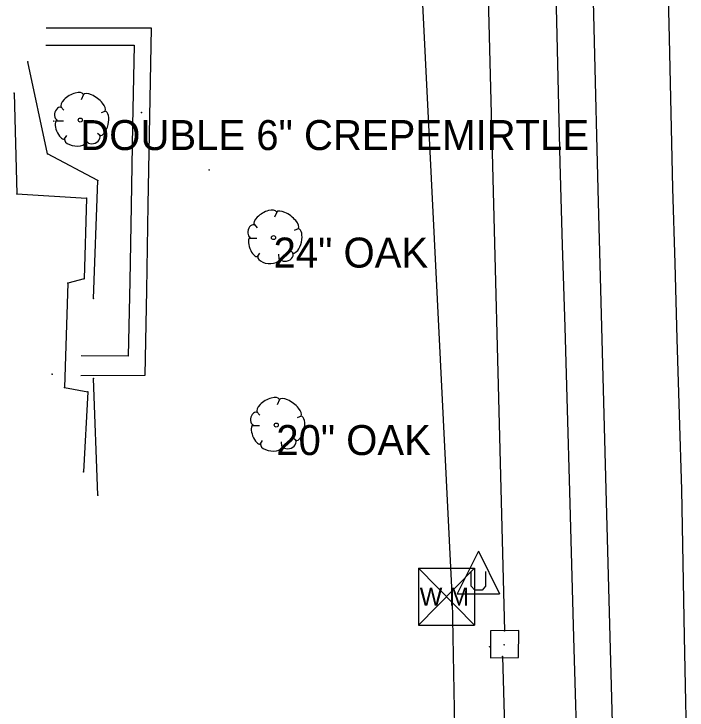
# Model space of a CAD drawing. Extents: x 1930288 to 1941089, y 588389 to 611475.
# Drawn here: x 1930777.7 to 1930890, y 597559.1 to 597675.1 of the extents above; entities that cross this region are included whole.
import ezdxf

# ---------------------------------------------------------------- set-up
doc = ezdxf.new("R2010")
doc.units = 0
for name, color, linetype in [('S_BUILDING', 7, 'Continuous'), ('S_DRG_PT_SYM', 7, 'Continuous'), ('S_DROP_INLET', 7, 'Continuous'), ('S_EDGE_PAVEMENT', 7, 'Continuous'), ('S_MSC_PT_SYM', 7, 'Continuous'), ('S_PAVEMENT_CROWN', 7, 'Continuous'), ('S_SHOULDER', 7, 'Continuous'), ('S_SIDEWALK', 7, 'Continuous'), ('S_STORM_SEWER', 7, 'Continuous'), ('S_STR_PT_SYM', 7, 'Continuous'), ('S_TREE', 7, 'Continuous'), ('S_TREE_ANNOT', 7, 'Continuous'), ('S_UNDERGROUND_CABLE', 7, 'Continuous'), ('S_UTL_PT_SYM', 7, 'Continuous'), ('S_WATER_UTILITIES', 7, 'Continuous')]:
    doc.layers.add(name, color=color, linetype=linetype)

msp = doc.modelspace()

# ---------------------------------------------------------------- linework, layer by layer
at = {"layer": 'S_BUILDING'}
for p, q in [((1930777.79, 597661.9), (1930778.25, 597645.11)), ((1930778.25, 597645.11), (1930789.85, 597644.43)), ((1930789.85, 597644.43), (1930789.43, 597630.99)), ((1930786.71, 597630.23), (1930786.18, 597612.84)), ((1930789.43, 597630.99), (1930786.71, 597630.23)), ((1930786.18, 597612.84), (1930790.09, 597612.14)), ((1930790.09, 597612.14), (1930789.32, 597598.78))]:
    msp.add_line(p, q, dxfattribs=at)
at = {"layer": 'S_DRG_PT_SYM'}
msp.add_lwpolyline([(1930859.51, 597569.98), (1930859.51, 597570.03), (1930859.51, 597569.98), (1930859.46, 597569.98), (1930859.51, 597569.98), (1930859.51, 597569.93), (1930859.51, 597569.98), (1930859.56, 597569.98)], dxfattribs=at)
at = {"layer": 'S_DROP_INLET'}
for points in [[(1930857.24, 597572.29), (1930857.22, 597567.78), (1930861.91, 597567.86), (1930861.93, 597572.36)], [(1930861.93, 597572.36), (1930857.24, 597572.29)]]:
    msp.add_lwpolyline(points, dxfattribs=at)
at = {"layer": 'S_EDGE_PAVEMENT'}
msp.add_lwpolyline([(1930870.73, 597810.89), (1930871.29, 597787.65), (1930871.95, 597765.34), (1930872.62, 597743.02), (1930873.25, 597719.11), (1930873.88, 597695.2), (1930874.49, 597670.52), (1930875.1, 597645.85), (1930875.43, 597633.35), (1930875.77, 597620.85), (1930876.1, 597608.34), (1930876.44, 597595.84), (1930877.12, 597571.29), (1930877.79, 597546.75)], dxfattribs=at)
at = {"layer": 'S_MSC_PT_SYM'}
for points in [[(1930780.05, 597667.14), (1930780.05, 597667.19), (1930780.05, 597667.14), (1930780, 597667.14), (1930780.05, 597667.14), (1930780.05, 597667.09), (1930780.05, 597667.14), (1930780.1, 597667.14)], [(1930799.01, 597658.7), (1930799.01, 597658.75), (1930799.01, 597658.7), (1930798.96, 597658.7), (1930799.01, 597658.7), (1930799.01, 597658.65), (1930799.01, 597658.7), (1930799.06, 597658.7)], [(1930784.38, 597657.27), (1930784.38, 597657.32), (1930784.38, 597657.27), (1930784.33, 597657.27), (1930784.38, 597657.27), (1930784.38, 597657.22), (1930784.38, 597657.27), (1930784.43, 597657.27)], [(1930783.36, 597651.78), (1930783.36, 597651.83), (1930783.36, 597651.78), (1930783.31, 597651.78), (1930783.36, 597651.78), (1930783.36, 597651.73), (1930783.36, 597651.78), (1930783.41, 597651.78)], [(1930810.3, 597649.11), (1930810.3, 597649.16), (1930810.3, 597649.11), (1930810.25, 597649.11), (1930810.3, 597649.11), (1930810.3, 597649.06), (1930810.3, 597649.11), (1930810.35, 597649.11)], [(1930791.76, 597647.37), (1930791.76, 597647.42), (1930791.76, 597647.37), (1930791.71, 597647.37), (1930791.76, 597647.37), (1930791.76, 597647.32), (1930791.76, 597647.37), (1930791.81, 597647.37)], [(1930790.99, 597627.66), (1930790.99, 597627.71), (1930790.99, 597627.66), (1930790.94, 597627.66), (1930790.99, 597627.66), (1930790.99, 597627.61), (1930790.99, 597627.66), (1930791.04, 597627.66)], [(1930784.1, 597615.07), (1930784.1, 597615.12), (1930784.1, 597615.07), (1930784.05, 597615.07), (1930784.1, 597615.07), (1930784.1, 597615.02), (1930784.1, 597615.07), (1930784.15, 597615.07)], [(1930790.99, 597614.35), (1930790.99, 597614.4), (1930790.99, 597614.35), (1930790.94, 597614.35), (1930790.99, 597614.35), (1930790.99, 597614.3), (1930790.99, 597614.35), (1930791.04, 597614.35)], [(1930791.72, 597594.91), (1930791.72, 597594.96), (1930791.72, 597594.91), (1930791.67, 597594.91), (1930791.72, 597594.91), (1930791.72, 597594.86), (1930791.72, 597594.91), (1930791.77, 597594.91)], [(1930859.53, 597572.29), (1930859.53, 597572.34), (1930859.53, 597572.29), (1930859.48, 597572.29), (1930859.53, 597572.29), (1930859.53, 597572.24), (1930859.53, 597572.29), (1930859.58, 597572.29)], [(1930857.03, 597569.65), (1930857.03, 597569.7), (1930857.03, 597569.65), (1930856.98, 597569.65), (1930857.03, 597569.65), (1930857.03, 597569.6), (1930857.03, 597569.65), (1930857.08, 597569.65)], [(1930859.23, 597567.99), (1930859.23, 597568.04), (1930859.23, 597567.99), (1930859.18, 597567.99), (1930859.23, 597567.99), (1930859.23, 597567.94), (1930859.23, 597567.99), (1930859.28, 597567.99)]]:
    msp.add_lwpolyline(points, dxfattribs=at)
at = {"layer": 'S_PAVEMENT_CROWN'}
msp.add_lwpolyline([(1930883.18, 597810.9), (1930883.85, 597787.85), (1930884.29, 597765.72), (1930884.74, 597743.6), (1930885.58, 597719.82), (1930886.42, 597696.04), (1930886.99, 597671.07), (1930887.57, 597646.1), (1930887.95, 597633.52), (1930888.32, 597620.95), (1930888.7, 597608.37), (1930889.08, 597595.8), (1930889.54, 597571.36), (1930890, 597546.92)], dxfattribs=at)
at = {"layer": 'S_SHOULDER'}
msp.add_lwpolyline([(1930864.57, 597814.62), (1930865.11, 597791.12), (1930865.66, 597767.61), (1930866.16, 597750.17), (1930866.67, 597732.73), (1930867.13, 597715.12), (1930867.6, 597697.51), (1930868.2, 597673.9), (1930868.81, 597650.28), (1930869.2, 597636.59), (1930869.59, 597622.9), (1930869.98, 597609.21), (1930870.37, 597595.52), (1930871.07, 597571.18), (1930871.77, 597546.85)], dxfattribs=at)
at = {"layer": 'S_SIDEWALK'}
for points in [[(1930788.91, 597614.87), (1930799.65, 597614.89), (1930799.89, 597629.09), (1930800.13, 597643.29), (1930800.42, 597658.02), (1930800.71, 597672.75), (1930783.1, 597672.75)], [(1930783.08, 597669.91), (1930797.77, 597669.93), (1930797.53, 597656.54), (1930797.29, 597643.16), (1930797.06, 597630.6), (1930796.82, 597618.05), (1930788.94, 597618.11)]]:
    msp.add_lwpolyline(points, dxfattribs=at)
at = {"layer": 'S_STORM_SEWER'}
for p, q in [((1930856.5, 597691.72), (1930859.53, 597572.29)), ((1930859.23, 597567.99), (1930861.97, 597466.22))]:
    msp.add_line(p, q, dxfattribs=at)
at = {"layer": 'S_STR_PT_SYM'}
for points in [[(1930777.79, 597661.9), (1930777.79, 597661.95), (1930777.79, 597661.9), (1930777.74, 597661.9), (1930777.79, 597661.9), (1930777.79, 597661.85), (1930777.79, 597661.9), (1930777.84, 597661.9)], [(1930778.25, 597645.11), (1930778.25, 597645.16), (1930778.25, 597645.11), (1930778.2, 597645.11), (1930778.25, 597645.11), (1930778.25, 597645.06), (1930778.25, 597645.11), (1930778.3, 597645.11)], [(1930789.85, 597644.43), (1930789.85, 597644.48), (1930789.85, 597644.43), (1930789.8, 597644.43), (1930789.85, 597644.43), (1930789.85, 597644.38), (1930789.85, 597644.43), (1930789.9, 597644.43)], [(1930786.71, 597630.23), (1930786.71, 597630.28), (1930786.71, 597630.23), (1930786.66, 597630.23), (1930786.71, 597630.23), (1930786.71, 597630.18), (1930786.71, 597630.23), (1930786.76, 597630.23)], [(1930789.43, 597630.99), (1930789.43, 597631.04), (1930789.43, 597630.99), (1930789.38, 597630.99), (1930789.43, 597630.99), (1930789.43, 597630.94), (1930789.43, 597630.99), (1930789.48, 597630.99)], [(1930786.18, 597612.84), (1930786.18, 597612.89), (1930786.18, 597612.84), (1930786.13, 597612.84), (1930786.18, 597612.84), (1930786.18, 597612.79), (1930786.18, 597612.84), (1930786.23, 597612.84)], [(1930790.09, 597612.14), (1930790.09, 597612.19), (1930790.09, 597612.14), (1930790.04, 597612.14), (1930790.09, 597612.14), (1930790.09, 597612.09), (1930790.09, 597612.14), (1930790.14, 597612.14)], [(1930789.32, 597598.78), (1930789.32, 597598.83), (1930789.32, 597598.78), (1930789.27, 597598.78), (1930789.32, 597598.78), (1930789.32, 597598.73), (1930789.32, 597598.78), (1930789.37, 597598.78)]]:
    msp.add_lwpolyline(points, dxfattribs=at)
at = {"layer": 'S_TREE'}
for p, q in [((1930783.36, 597651.78), (1930780.05, 597667.14)), ((1930789.37, 597661.67), (1930788.98, 597660.82)), ((1930785.57, 597659.66), (1930786.07, 597659.08)), ((1930792.93, 597658.88), (1930792.27, 597658.61)), ((1930784.91, 597657.33), (1930786.03, 597657.33)), ((1930786.07, 597654.16), (1930786.54, 597654.85)), ((1930789.75, 597653.89), (1930789.68, 597654.66)), ((1930792.16, 597654.78), (1930791.69, 597655.2)), ((1930791.76, 597647.37), (1930783.36, 597651.78)), ((1930790.99, 597627.66), (1930791.76, 597647.37)), ((1930821.6, 597642.08), (1930821.21, 597641.23)), ((1930817.8, 597640.07), (1930818.3, 597639.49)), ((1930825.16, 597639.29), (1930824.5, 597639.02)), ((1930817.14, 597637.74), (1930818.27, 597637.74)), ((1930818.3, 597634.57), (1930818.77, 597635.26)), ((1930821.99, 597634.3), (1930821.91, 597635.07)), ((1930824.39, 597635.19), (1930823.92, 597635.61)), ((1930791.72, 597594.91), (1930790.99, 597614.35)), ((1930822.05, 597610.84), (1930821.66, 597609.98)), ((1930818.25, 597608.82), (1930818.76, 597608.24)), ((1930825.62, 597608.05), (1930824.96, 597607.78)), ((1930817.6, 597606.5), (1930818.72, 597606.5)), ((1930818.76, 597603.32), (1930819.22, 597604.02)), ((1930822.44, 597603.05), (1930822.36, 597603.82)), ((1930824.84, 597603.94), (1930824.38, 597604.37))]:
    msp.add_line(p, q, dxfattribs=at)
for centre in [(1930788.81, 597657.43), (1930821.04, 597637.84), (1930821.49, 597606.59)]:
    msp.add_circle(centre, 0.341, dxfattribs=at)
for centre, major_axis, ratio, start_param, end_param in [((1930787.47, 597660.63), (1.86, 1.08), 0.471018, 0, 3.141593), ((1930791.13, 597660.31), (-1.81, 1.36), 0.405113, 3.141593, 6.283186), ((1930785.24, 597658.52), (0.31, 1.03), 0.646762, 0, 3.141593), ((1930792.48, 597656.9), (0.46, 2.04), 0.482994, 3.141593, 6.283185), ((1930785.54, 597655.87), (-0.61, 1.6), 0.420543, 6.283185, 9.424777), ((1930790.96, 597654.38), (1.09, 0.46), 0.711534, 3.141592, 6.283185), ((1930788, 597654.09), (-1.83, 0.19), 0.529943, 0, 3.141593), ((1930819.7, 597641.04), (1.86, 1.08), 0.471018, 0, 3.141593), ((1930823.36, 597640.72), (-1.81, 1.36), 0.405113, 3.141593, 6.283186), ((1930817.47, 597638.93), (0.31, 1.03), 0.646762, 0, 3.141593), ((1930824.71, 597637.31), (0.46, 2.04), 0.482994, 3.141593, 6.283185), ((1930817.77, 597636.28), (-0.61, 1.6), 0.420543, 6.283185, 9.424777), ((1930820.23, 597634.49), (-1.83, 0.19), 0.529943, 0, 3.141593), ((1930823.19, 597634.79), (1.09, 0.46), 0.711534, 3.141592, 6.283185), ((1930820.16, 597609.79), (1.86, 1.08), 0.471018, 0, 3.141593), ((1930823.81, 597609.47), (-1.81, 1.36), 0.405113, 3.141593, 6.283186), ((1930817.92, 597607.68), (0.31, 1.03), 0.646762, 0, 3.141593), ((1930825.17, 597606.06), (0.46, 2.04), 0.482994, 3.141593, 6.283185), ((1930818.23, 597605.03), (-0.61, 1.6), 0.420543, 6.283185, 9.424777), ((1930820.69, 597603.25), (-1.83, 0.19), 0.529943, 0, 3.141593), ((1930823.65, 597603.54), (1.09, 0.46), 0.711534, 3.141592, 6.283185)]:
    msp.add_ellipse(centre, major_axis=major_axis, ratio=ratio, start_param=start_param, end_param=end_param, dxfattribs=at)
at = {"layer": 'S_UNDERGROUND_CABLE'}
for p, q in [((1930855.21, 597585.57), (1930851.68, 597578.48)), ((1930855.21, 597585.57), (1930858.7, 597578.48)), ((1930854.01, 597579.72), (1930854.01, 597582.16)), ((1930856.37, 597582.16), (1930856.37, 597579.72)), ((1930854.63, 597579.06), (1930854.01, 597579.72)), ((1930855.83, 597579.06), (1930854.63, 597579.06)), ((1930856.37, 597579.72), (1930855.83, 597579.06)), ((1930851.68, 597578.48), (1930858.7, 597578.48))]:
    msp.add_line(p, q, dxfattribs=at)
at = {"layer": 'S_UTL_PT_SYM'}
for points in [[(1930850.82, 597577.28), (1930850.82, 597577.33), (1930850.82, 597577.28), (1930850.77, 597577.28), (1930850.82, 597577.28), (1930850.82, 597577.23), (1930850.82, 597577.28), (1930850.87, 597577.28)], [(1930859.53, 597572.29), (1930859.53, 597572.34), (1930859.53, 597572.29), (1930859.48, 597572.29), (1930859.53, 597572.29), (1930859.53, 597572.24), (1930859.53, 597572.29), (1930859.58, 597572.29)], [(1930859.51, 597569.98), (1930859.51, 597570.03), (1930859.51, 597569.98), (1930859.46, 597569.98), (1930859.51, 597569.98), (1930859.51, 597569.93), (1930859.51, 597569.98), (1930859.56, 597569.98)], [(1930859.23, 597567.99), (1930859.23, 597568.04), (1930859.23, 597567.99), (1930859.18, 597567.99), (1930859.23, 597567.99), (1930859.23, 597567.94), (1930859.23, 597567.99), (1930859.28, 597567.99)]]:
    msp.add_lwpolyline(points, dxfattribs=at)
at = {"layer": 'S_WATER_UTILITIES'}
for p, q in [((1930841.28, 597769.64), (1930850.82, 597577.28)), ((1930845.2, 597582.75), (1930854.54, 597582.75)), ((1930845.2, 597582.75), (1930845.2, 597573.25)), ((1930845.2, 597582.75), (1930854.54, 597573.25)), ((1930854.54, 597582.75), (1930845.2, 597573.25)), ((1930854.54, 597582.75), (1930854.54, 597573.25)), ((1930850.82, 597577.28), (1930853.31, 597453.42)), ((1930845.2, 597573.25), (1930854.54, 597573.25))]:
    msp.add_line(p, q, dxfattribs=at)

# ---------------------------------------------------------------- texts
at = {"layer": 'S_TREE_ANNOT'}
for s, p in [('DOUBLE 6" CREPEMIRTLE', (1930788.81, 597652.43)), ('24" OAK', (1930821.04, 597632.84)), ('20" OAK', (1930821.49, 597601.59))]:
    msp.add_text(s, height=5, dxfattribs=at).set_placement(p)
at = {"layer": 'S_WATER_UTILITIES'}
msp.add_text('W M', height=3, rotation=360, dxfattribs=at).set_placement((1930845.41, 597576.51))

doc.saveas('drawing.dxf')
